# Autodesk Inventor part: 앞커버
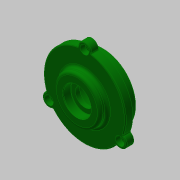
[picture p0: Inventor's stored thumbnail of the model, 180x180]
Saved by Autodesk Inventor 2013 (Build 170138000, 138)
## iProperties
Created: 2016-05
Part Number: 앞커버
Document SubType Name: Modeling
Designer: mduedu
Density: 2.71 g/cm^3
Material: 알루미늄 6061
Author: mduedu
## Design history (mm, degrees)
sketch "스케치1"
  geometry: C1 r 36 at (0, 0); C2 r 44 at (0, 0); 1 further point
  constraints: 2 centre point, 2 coincident
  dimensions: "d33" = 88 diameter of C2; "d34" = 72 diameter of C1
extrude "돌출1" new body sketch "스케치1" distance "d0" = 8; taper "d1" = 0 deg
extrude "돌출2" join sketch "스케치1" distance "d2" = 8; taper "d3" = 0 deg; dims "d35" = 12, "d36" = 0
sketch "스케치6"
  geometry: C1 r 25 at (0, 0); 2 further points
  constraints: 2 coincident, 1 centre point
  dimensions: "d42" = 50 diameter of C1
extrude "돌출4" join sketch "스케치6" distance "d43" = 8; taper "d44" = 0 deg
sketch "스케치9"
  geometry: C1 r 7 at (0, 44); 2 further points
  constraints: 2 vertical alignment, 1 centre point, 1 other
  dimensions: "d70" = 14 diameter of C1
extrude "돌출5" join sketch "스케치9" stored distance "d71" = 10; taper "d72" = 0 deg
fillet "모깎기9" dims "d76" = 1
sketch "스케치10"
  geometry: C1 r 25 at (0, 0) reference; A1 r 1 centre (-42.349, -15.218) between (-41.818, -16.066) and (-41.408, -14.88) reference; A2 r 7 centre (-38.105, -22) between (-41.818, -16.066) and (-34.823, -28.183) reference; A3 r 1 centre (-34.354, -29.066) between (-33.59, -28.42) and (-34.823, -28.183) reference; A4 r 44 centre (0, 0) between (-33.59, -28.42) and (33.59, -28.42) reference; A5 r 1 centre (34.354, -29.066) between (34.823, -28.183) and (33.59, -28.42) reference; A6 r 7 centre (38.105, -22) between (34.823, -28.183) and (41.818, -16.066) reference; A7 r 1 centre (42.349, -15.218) between (41.408, -14.88) and (41.818, -16.066) reference; A8 r 44 centre (0, 0) between (41.408, -14.88) and (7.817, 43.3) reference; A9 r 1 centre (7.995, 44.284) between (6.996, 44.249) and (7.817, 43.3) reference; A10 r 7 centre (0, 44) between (6.996, 44.249) and (-6.996, 44.249) reference; A11 r 1 centre (-7.995, 44.284) between (-7.817, 43.3) and (-6.996, 44.249) reference; A12 r 44 centre (0, 0) between (-7.817, 43.3) and (-41.408, -14.88) reference; 4 further points
  constraints: 3 coincident
hole "구멍3" sketch "스케치10" at (0, 44), (-38.105, -22), (38.105, -22) diameter "d77" = 5.5; stored, may be unused: countersink angle "d81" = 90 deg, drill point angle "d83" = 118 deg; dims "d78" = 6, "d79" = 9.5, "d80" = 5.4, "d82" = 8
fillet "모깎기10" dims "d84" = 1
fillet "모깎기7" dims "d68" = 3
fillet "모깎기8" dims "d69" = 3
sketch "스케치4"
  geometry: L1 (0, -12)-(0, 16); L2 (-20, -12)-(-20, 0); L3 (-20, 0)-(-15, 0); L4 (-15, 0)-(-15, 3); L5 (-15, 3)-(-10, 3); L6 (-10, 3)-(-10, 7.7); L7 (-10, 7.7)-(-15, 7.7); L8 (-15, 7.7)-(-15, 16); L9 (36, -12)-(-36, -12) reference; L10 (25, 16)-(-25, 16) reference; 1 further point
  constraints: 16 end point, 6 parallel, 3 point on line, 2 midpoint, 1 perpendicular, 1 vertical
  dimensions: "d15" = 40 diameter of L2 L1; "d16" = 30 diameter of L8 L1; "d18" = 12 distance of L2.start L2.end; "d19" = 3 distance of L3.end L4.end; "d20" = 30 diameter of L4 L1; "d21" = 20 diameter of L6 L1; "d45" = 8.3 distance of L7.end L8.end
revolve "회전1" sketch "스케치4" stored, may be unused: angle "d22" = 90 deg
fillet "모깎기2" dims "d23" = 3
fillet "모깎기3" dims "d24" = 0.3
chamfer "모따기2" distance "d46" = 1; stored, may be unused: second distance "d47" = 2, angle "d48" = 45 deg
chamfer "모따기3" distance "d64" = 0.8; stored, may be unused: second distance "d65" = 2, angle "d66" = 30 deg
node "솔리드1"
pattern_circular "원형 패턴1" dims angle "d74" = 360 deg
node "투영된 루프1"
